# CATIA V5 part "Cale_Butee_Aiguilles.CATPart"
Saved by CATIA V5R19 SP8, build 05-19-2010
Part number: Cale_Butee_Aiguilles
Nomenclature: 70_g
Bounding box of the stored display mesh (mm): x -13 to 13, y -12.99 to 12.99, z 0 to 4
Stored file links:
  C:\Users\rphgr\Desktop\0_Tapis_TC520B_vitesse\Cale_Butee_Aiguilles.CATPart
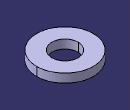
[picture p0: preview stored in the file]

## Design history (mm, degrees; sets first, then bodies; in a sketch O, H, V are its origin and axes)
Body1 (main body)
  AxisSystem1: origin (0, 0, 0), X (1, 0, 0), Y (0, 1, 0), Z (0, 0, 1)
  Sketch1 on XY plane of AxisSystem1, origin (0, 0, 0), H (1, 0, 0), V (0, 1, 0)
    circle A1 centre (0, 0) radius 6.1
    point P1 (0, 0)
    circle A2 centre (0, 0) radius 13
    radius A1 = 6.1
    radius A2 = 13
    coincidence: P1 V
    concentricity: A2 A1
  Pad1: profile Sketch1, direction (0, 0, 1), length 4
